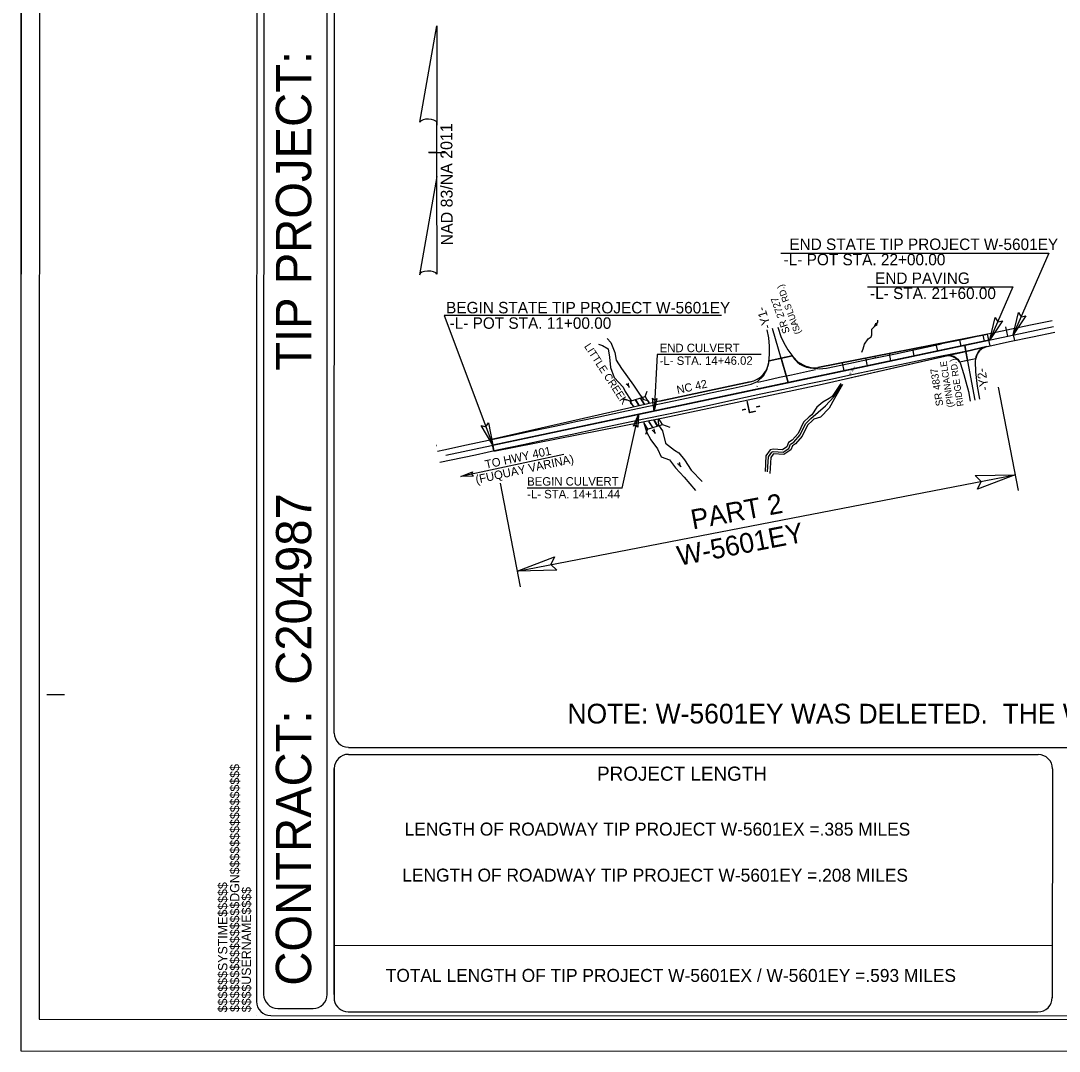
# Model space of a CAD drawing. Extents: x 2105791 to 2114488, y 667759 to 673441.
# Drawn here: x 2105791 to 2109589, y 667759 to 671528 of the extents above; entities that cross this region are included whole.
import ezdxf

# ---------------------------------------------------------------- set-up
doc = ezdxf.new("R2010")
doc.units = 0
for name, color, linetype in [('Default', 7, 'Continuous'), ('Exist Hydro Jurisdictional Stream or Body of Water', 7, 'Continuous'), ('Exist Hydro Stream Flow Arrow CELL', 7, 'Continuous'), ('Exist Hydro Stream or Body of Water', 7, 'Continuous'), ('Exist Roads EOP', 7, 'Continuous'), ('Exist Structure Minor Pipes RCP 48 Inch Text', 7, 'Continuous'), ('Old_Level_1', 7, 'Continuous'), ('Prop Dimension', 7, 'Continuous'), ('Prop Dimension Text', 7, 'Continuous'), ('Prop DSN Text', 7, 'Continuous'), ('Prop EOT', 7, 'Continuous'), ('Prop Horizontal Alignment', 7, 'Continuous'), ('Prop North Arrow NAD83 for Plan Sheets CELL', 7, 'Continuous'), ('Prop Shade Light', 7, 'Continuous'), ('Scratch_Level_3', 7, 'Continuous'), ('Sheet Cutting Line CELL', 7, 'Continuous'), ('Sheet Data Field CELL', 7, 'Continuous'), ('Sheet Plot Border Inside CELL', 7, 'Continuous'), ('Sheet Plot Border Outside CELL', 7, 'Continuous'), ('Sheet Title CELL', 7, 'Continuous'), ('Typical Terminator CELL', 7, 'Continuous')]:
    doc.layers.add(name, color=color, linetype=linetype)

msp = doc.modelspace()

# ---------------------------------------------------------------- linework, layer by layer
at = {"layer": 'Default'}
msp.add_arc((2108867.2, 670316.4), 52.5, 335.702, 340.6416, dxfattribs=at)
at = {"layer": 'Exist Hydro Jurisdictional Stream or Body of Water'}
for points in [[(2108867.2, 670316.4), (2108871.4, 670328.4), (2108876.9, 670345.1), (2108890.4, 670364.5), (2108901, 670372.3), (2108904.2, 670379.1), (2108903.8, 670400.7), (2108916, 670412.7), (2108926.2, 670426.1), (2108925.7, 670433.4)], [(2107935.6, 670365.5), (2107949, 670351.7), (2107964.3, 670314.3), (2107968.2, 670286.5), (2107988.4, 670255.8), (2108010.6, 670226.4), (2108032.1, 670194.8), (2108056.2, 670158.6), (2108069, 670143.1), (2108085.6, 670139.7), (2108089.3, 670128.6)], [(2107903.4, 670345.8), (2107918.5, 670340.3), (2107939.8, 670328.5), (2107944.2, 670298.1), (2107948.2, 670260), (2107961, 670223.9), (2107994.4, 670187.5), (2108001.1, 670172.4), (2108021.7, 670140.9), (2108022.4, 670133.9), (2108021.4, 670129.5), (2108027.8, 670122.3), (2108033.3, 670118)], [(2108070.2, 670057.1), (2108079.6, 670025.3), (2108094.8, 669995.7), (2108120.3, 669962), (2108133.4, 669933.8), (2108163.2, 669922.3), (2108185.5, 669893.1), (2108216.9, 669859), (2108259.2, 669809.7)], [(2108120.8, 670069.8), (2108121.8, 670065.2), (2108122.9, 670048.8), (2108138, 670028.9), (2108149.5, 669983.5), (2108181.7, 669958.1), (2108198.3, 669947.7), (2108218.1, 669921.8), (2108242.6, 669885.1), (2108282.7, 669843.6)]]:
    msp.add_lwpolyline(points, dxfattribs=at)
at = {"layer": 'Exist Hydro Stream Flow Arrow CELL'}
for p, q in [((2108914.9, 670412.4), (2108914.9, 670412.4)), ((2108012.4, 670194.9), (2108012.4, 670194.9)), ((2108107.5, 670025.8), (2108107.5, 670025.8)), ((2108200.3, 669904.1), (2108200.3, 669904.1))]:
    msp.add_line(p, q, dxfattribs=at)
for points in [[(2108917.6, 670421.6), (2108916.9, 670419.2), (2108915.9, 670416.8), (2108914.8, 670414.4), (2108913.6, 670412.2), (2108912.2, 670410), (2108910.7, 670407.8), (2108909.2, 670405.8)], [(2108923.7, 670416.4), (2108921.3, 670415.3), (2108919.1, 670413.9), (2108916.9, 670412.6), (2108914.9, 670411.1), (2108912.9, 670409.4), (2108910.9, 670407.6), (2108909.2, 670405.8)], [(2108004.7, 670200.6), (2108006.8, 670199.1), (2108008.7, 670197.3), (2108010.5, 670195.5), (2108012.2, 670193.6), (2108013.8, 670191.5), (2108015.3, 670189.4), (2108016.6, 670187.2)], [(2108011.7, 670204.5), (2108011.9, 670201.9), (2108012.4, 670199.3), (2108012.9, 670196.8), (2108013.6, 670194.4), (2108014.5, 670191.9), (2108015.5, 670189.5), (2108016.6, 670187.2)], [(2108099.7, 670031.4), (2108101.7, 670029.9), (2108103.7, 670028.1), (2108105.6, 670026.4), (2108107.3, 670024.5), (2108108.9, 670022.5), (2108110.4, 670020.3), (2108111.8, 670018.2)], [(2108106.6, 670035.4), (2108106.9, 670032.8), (2108107.4, 670030.3), (2108108, 670027.7), (2108108.7, 670025.3), (2108109.6, 670022.9), (2108110.6, 670020.5), (2108111.8, 670018.2)], [(2108192.5, 669909.7), (2108194.5, 669908.2), (2108196.5, 669906.4), (2108198.4, 669904.6), (2108200.1, 669902.7), (2108201.7, 669900.7), (2108203.2, 669898.6), (2108204.6, 669896.4)], [(2108199.4, 669913.6), (2108199.7, 669911.1), (2108200.2, 669908.5), (2108200.8, 669906), (2108201.5, 669903.6), (2108202.4, 669901.1), (2108203.4, 669898.7), (2108204.6, 669896.4)]]:
    msp.add_lwpolyline(points, dxfattribs=at)
at = {"layer": 'Exist Hydro Stream or Body of Water'}
for p, q in [((2108790.2, 670201.1), (2108758.5, 670154.2)), ((2108796.2, 670197.5), (2108767.7, 670146.6)), ((2108724.2, 670133.5), (2108703, 670115.3)), ((2108703, 670115.3), (2108683.7, 670087.3)), ((2108715.6, 670077.9), (2108691.8, 670071.1))]:
    msp.add_line(p, q, dxfattribs=at)
for points in [[(2108680.9, 670073.2), (2108734, 670119.7), (2108764.3, 670153.3), (2108777, 670170.9), (2108793.1, 670198.7)], [(2108758.5, 670154.2), (2108747.2, 670146.1), (2108724.2, 670133.5)], [(2108767.7, 670146.6), (2108767.7, 670146.6), (2108747.4, 670111)], [(2108747.4, 670111), (2108715.6, 670077.9)], [(2108683.7, 670087.3), (2108675, 670079.6), (2108653.6, 670059.8), (2108633.8, 670018.4), (2108612.5, 669993.9), (2108599.3, 669985.3), (2108592.9, 669970), (2108577, 669959.4), (2108542.3, 669961.3), (2108532.2, 669958.4), (2108516.6, 669936.7), (2108513.8, 669879.1)], [(2108691.8, 670071.1), (2108686.7, 670066.7), (2108668, 670049.2), (2108648.5, 670008.7), (2108624, 669980.5), (2108613.4, 669973.6), (2108607.1, 669958.5), (2108581.9, 669941.5), (2108544.2, 669943.7), (2108542.9, 669943.3), (2108533.9, 669930.7), (2108531, 669872.8)], [(2108579.4, 669950.4), (2108579.4, 669950.4), (2108600, 669964.3), (2108606.3, 669979.5), (2108618.2, 669987.2), (2108641.1, 670013.5), (2108660.8, 670054.5), (2108680.9, 670073.2)], [(2108522.5, 669878.7), (2108525.2, 669933.7), (2108537.5, 669950.9), (2108543.3, 669952.5), (2108579.4, 669950.4)]]:
    msp.add_lwpolyline(points, dxfattribs=at)
at = {"layer": 'Exist Roads EOP'}
for points in [[(2107314.7, 669954), (2107338.6, 669959.2), (2107421.5, 669977.3), (2107501.1, 669994), (2107583.8, 670011.2), (2107661.5, 670028.3), (2107744.5, 670046), (2107827, 670063.4), (2107905.3, 670079.8), (2107989.2, 670097.4), (2108069.8, 670114.8), (2108150.1, 670132), (2108231.9, 670149.3), (2108314.1, 670167.1), (2108396.2, 670184.8), (2108462.7, 670199.1), (2108486, 670209.3), (2108507.3, 670229.4), (2108520.3, 670254.1), (2108527.3, 670279.6), (2108530, 670308), (2108529.7, 670338.5), (2108527, 670368.5), (2108521.1, 670397.2)], [(2108559.4, 670407.5), (2108570.6, 670374), (2108581.5, 670350.3), (2108596.6, 670325.2), (2108614.4, 670300.5), (2108634.4, 670279.1), (2108662, 670264.9), (2108690, 670257.1), (2108710.7, 670255.1), (2108738.2, 670257.6), (2108819.7, 670274.9), (2108905, 670292.6), (2108989.7, 670310.6), (2109074.1, 670328.3), (2109158.7, 670346.2)], [(2109563.8, 670431.3), (2109483.4, 670414.5), (2109397.7, 670396.6), (2109310.7, 670378.5), (2109238.7, 670362.8), (2109158.7, 670346.2)], [(2109170.6, 670304.6), (2109183.6, 670307.3), (2109246.2, 670320.3), (2109320.4, 670335.6), (2109407, 670354.7), (2109491.5, 670372.5), (2109572.5, 670389.6)], [(2109170.6, 670304.6), (2109183.6, 670307.3), (2109246.2, 670320.3), (2109320.4, 670335.6), (2109407, 670354.7), (2109491.5, 670372.5), (2109572.5, 670389.6)], [(2109298.5, 670143.9), (2109290.6, 670191.6), (2109284.6, 670244), (2109283.1, 670282.4), (2109285.8, 670301.9), (2109295.1, 670321), (2109301.7, 670326.8), (2109317.8, 670334.5)], [(2109170.6, 670304.5), (2109092.9, 670288.3), (2109012.1, 670271.1), (2108929.6, 670253.7), (2108836.6, 670233.9), (2108753.2, 670216), (2108668.6, 670198.6), (2108581.2, 670179.9), (2108498.1, 670162.3), (2108414.1, 670143.9), (2108331.9, 670126.2), (2108247.6, 670108), (2108159.9, 670089.8), (2108070, 670071), (2107982.8, 670052.5), (2107896.4, 670034.2), (2107808.1, 670015.5), (2107717.3, 669996.3), (2107628.3, 669977.1), (2107539.6, 669958.4), (2107453.9, 669939.9), (2107365.5, 669921.4), (2107323.4, 669912.2)], [(2109183.8, 670306.4), (2109203.3, 670301.7), (2109217.9, 670290.7), (2109226.5, 670276.5), (2109240.5, 670234.4), (2109248, 670207.5), (2109256.7, 670172.2), (2109263.6, 670137.3)], [(2108698, 670251.8), (2108653.6, 670241.7), (2108610, 670232.4), (2108565.9, 670223), (2108520.1, 670212.6), (2108486.3, 670205.4)], [(2108698, 670251.8), (2108653.6, 670241.7), (2108610, 670232.4), (2108565.9, 670223), (2108520.1, 670212.6), (2108486.3, 670205.4)]]:
    msp.add_lwpolyline(points, dxfattribs=at)
at = {"layer": 'Old_Level_1'}
for p, q in [((2107250.5, 671157.5), (2107312.9, 671509.5)), ((2107313.2, 671509.5), (2107312.9, 671509.5)), ((2107313.2, 671509.5), (2107312.9, 671509.5)), ((2107313.2, 671509.5), (2107313.1, 671146.5)), ((2107313.1, 670958.2), (2107313.1, 671157.1)), ((2107313.1, 671146.5), (2107313.1, 671156.8)), ((2107282.7, 671046.3), (2107282.4, 671046.3)), ((2107309.7, 671046.3), (2107282.7, 671046.3)), ((2107283.1, 671046.3), (2107343.9, 671046.3)), ((2107313.1, 670958.2), (2107249.6, 670599.4)), ((2107313.4, 670600.9), (2107313.1, 670958.2)), ((2109365.4, 670188.3), (2109438.5, 669810.2)), ((2107606, 669515.5), (2109427.4, 669867.4)), ((2107544, 669836.4), (2107617.1, 669458.2))]:
    msp.add_line(p, q, dxfattribs=at)
for centre, start_param, end_param in [((2107281.9, 671153.8), 0.216388, 2.908219), ((2107281.7, 670598.1), 0.201328, 3.141593)]:
    msp.add_ellipse(centre, major_axis=(32.1, -0.2), ratio=0.461098, start_param=start_param, end_param=end_param, dxfattribs=at)
at = {"layer": 'Prop Dimension'}
for p, q in [((2108074.6, 670153.4), (2108082.2, 670173.4)), ((2108020, 670136.9), (2107993.4, 670146.9)), ((2108020, 670136.9), (2108074.6, 670153.4)), ((2108033.1, 670116.3), (2108020, 670136.9)), ((2108037.6, 670142.2), (2108051.3, 670120.1)), ((2108038.8, 670142.6), (2108052.5, 670120.4)), ((2108056.2, 670147.8), (2108070.7, 670124.3)), ((2108057.1, 670148.1), (2108071.7, 670124.5)), ((2108074.6, 670153.4), (2108089.9, 670128.4)), ((2108069, 670058.5), (2108083.2, 670035)), ((2108087.2, 670062.4), (2108100.9, 670040.3)), ((2108088.2, 670062.6), (2108101.8, 670040.6)), ((2108106.4, 670066.5), (2108119.1, 670045.9)), ((2108107.6, 670066.8), (2108120.3, 670046.2)), ((2108137.8, 670051.5), (2108125.7, 670070.7)), ((2108083.2, 670035), (2108075.6, 670014.9)), ((2108083.2, 670035), (2108137.8, 670051.5)), ((2108137.8, 670051.5), (2108164.4, 670041.5))]:
    msp.add_line(p, q, dxfattribs=at)
at = {"layer": 'Prop Dimension Text'}
for p, q in [((2108118.6, 670307.3), (2108107.2, 670100.6)), ((2108498.4, 670307.2), (2108118.6, 670307.3)), ((2107990, 669818.3), (2108050.3, 670088.5)), ((2107777.1, 669942), (2107400, 669860.9)), ((2107990, 669818.3), (2107643.2, 669818.4))]:
    msp.add_line(p, q, dxfattribs=at)
at = {"layer": 'Prop DSN Text'}
for p, q in [((2108570.8, 670678.8), (2109551.4, 670678.7)), ((2109551.4, 670678.7), (2109420.8, 670379.1)), ((2108887.3, 670555.2), (2109419.8, 670555.1)), ((2109419.8, 670555.1), (2109335.2, 670361)), ((2108354.4, 670450.5), (2107339.1, 670450.6)), ((2107339.1, 670450.6), (2107517.2, 669975.5)), ((2109420.8, 670379.1), (2109425.2, 670358.5))]:
    msp.add_line(p, q, dxfattribs=at)
at = {"layer": 'Prop EOT'}
for p, q in [((2108706, 670259.8), (2109327.2, 670381.9)), ((2109336.3, 670339.1), (2109327.2, 670381.9)), ((2108722.4, 670198.8), (2109336.3, 670339.1)), ((2108527.8, 670284.6), (2108612.9, 670302.6)), ((2109224.1, 670280.4), (2109284.6, 670293.2)), ((2108126.9, 670137), (2108458.8, 670207.2)), ((2108140, 670075.4), (2108722.4, 670198.8)), ((2108484.4, 670190.6), (2108485.8, 670192.7)), ((2108126.9, 670137), (2107512.7, 669996.4)), ((2107521.6, 669954.5), (2108140, 670075.4)), ((2107521.6, 669954.5), (2107512.7, 669996.4))]:
    msp.add_line(p, q, dxfattribs=at)
for centre, radius, start, end in [((2109336.5, 670285.3), 52.5, 102.8715, 171.362), ((2108440.7, 670292.8), 87.5, 281.9495, 354.576), ((2108689.1, 670345.7), 87.5, 209.4773, 281.1199), ((2109181.4, 670249.9), 52.5, 35.5249, 102.8715)]:
    msp.add_arc(centre, radius, start, end, dxfattribs=at)
at = {"layer": 'Prop Horizontal Alignment'}
for p, q in [((2107346, 669939.2), (2109567.8, 670410.3)), ((2108597.8, 670204.6), (2108540.4, 670402.2)), ((2109281.1, 670140.9), (2109243.7, 670341.6))]:
    msp.add_line(p, q, dxfattribs=at)
at = {"layer": 'Prop Shade Light'}
for p, q in [((2109327.2, 670381.9), (2108706, 670259.8)), ((2109331.8, 670360.3), (2109243.7, 670341.6)), ((2109243.7, 670341.6), (2109331.8, 670360.3)), ((2109331.8, 670360.3), (2109327.2, 670381.9)), ((2109336.3, 670339.1), (2109331.8, 670360.3)), ((2108597.8, 670204.6), (2109243.7, 670341.6)), ((2109248, 670318.9), (2109243.7, 670341.6)), ((2109243.7, 670341.6), (2109248, 670318.9)), ((2109324.8, 670336.5), (2109248, 670318.9)), ((2108571.8, 670293.9), (2108527.8, 670284.6)), ((2108612.9, 670302.6), (2108571.8, 670293.9)), ((2108597.8, 670204.6), (2108571.8, 670293.9)), ((2108571.8, 670293.9), (2108597.8, 670204.6)), ((2109248, 670318.9), (2109169.7, 670301)), ((2109224.1, 670280.4), (2109254, 670286.7)), ((2109248, 670318.9), (2109254, 670286.7)), ((2109254, 670286.7), (2109248, 670318.9)), ((2109254, 670286.7), (2109284.6, 670293.2)), ((2108458.8, 670207.2), (2108126.9, 670137)), ((2107517.2, 669975.5), (2108597.8, 670204.6)), ((2108140, 670075.4), (2108722.4, 670198.8)), ((2108126.9, 670137), (2107513.2, 669996.5)), ((2107521.6, 669954.5), (2108140, 670075.4)), ((2107513.2, 669996.5), (2107517.2, 669975.5)), ((2107517.2, 669975.5), (2107521.6, 669954.5))]:
    msp.add_line(p, q, dxfattribs=at)
for points in [[(2109243.7, 670341.6), (2108597.8, 670204.6), (2107517.2, 669975.5)], [(2109248, 670318.9), (2109324.8, 670336.5), (2109336.3, 670339.1)], [(2108722.4, 670198.8), (2109169.7, 670301), (2109248, 670318.9)]]:
    msp.add_lwpolyline(points, dxfattribs=at)
for centre, radius, start, end in [((2109336.5, 670285.3), 52.5, 102.8715, 171.362), ((2108440.7, 670292.8), 87.5, 281.9495, 354.576), ((2108689.1, 670345.7), 87.5, 209.4773, 281.1199), ((2109181.4, 670249.9), 52.5, 35.5249, 102.8715)]:
    msp.add_arc(centre, radius, start, end, dxfattribs=at)
at = {"layer": 'Scratch_Level_3'}
for p, q in [((2109393, 670409), (2109400.3, 670374.8)), ((2109224.2, 670361.7), (2109229.1, 670338.5)), ((2109310.1, 670378.3), (2109314.7, 670356.6)), ((2109052.4, 670327.9), (2109057.9, 670302.2)), ((2109138.3, 670344.8), (2109143.5, 670320.3)), ((2108880.7, 670294.2), (2108886.7, 670265.9)), ((2108966.6, 670311), (2108972.3, 670284)), ((2108794.8, 670277.3), (2108801.1, 670247.7))]:
    msp.add_line(p, q, dxfattribs=at)
at = {"layer": 'Sheet Cutting Line CELL'}
msp.add_line((2105792, 673440.8), (2105791, 667760.7), dxfattribs=at)
at = {"layer": 'Sheet Data Field CELL'}
msp.add_line((2106653.4, 667889.7), (2106653.4, 667889.7), dxfattribs=at)
at = {"layer": 'Sheet Plot Border Inside CELL'}
msp.add_lwpolyline([(2105858.2, 667876.6), (2114463.6, 667875.1), (2114464.5, 673323.4), (2105859.1, 673324.8)], close=True, dxfattribs=at)
at = {"layer": 'Sheet Plot Border Outside CELL'}
msp.add_lwpolyline([(2114487.7, 673439.3), (2105792, 673440.8), (2105791, 667760.7), (2114486.8, 667759.2)], close=True, dxfattribs=at)
at = {"layer": 'Sheet Title CELL'}
for p, q in [((2106911.6, 667967.1), (2106912.5, 673234.1)), ((2106937.6, 668922.4), (2106938.3, 673234.1)), ((2105886.8, 669064.5), (2105951.3, 669064.5)), ((2106989.2, 668870.7), (2114321.7, 668869.5)), ((2106989.2, 668844.8), (2109512.2, 668844.4)), ((2106937.5, 668793.3), (2106937.4, 667945.6)), ((2106937.5, 667967), (2106937.5, 668793.3)), ((2109564.4, 668791.8), (2109563.5, 667955.1)), ((2106937.5, 668146.9), (2109563.9, 668146.5)), ((2106653.4, 667889.7), (2106653.4, 667889.7)), ((2106653.4, 667889.7), (2106653.4, 667889.7)), ((2106653.4, 667889.7), (2106653.4, 667889.7)), ((2106653.4, 667889.7), (2106653.4, 667889.7))]:
    msp.add_line(p, q, dxfattribs=at)
for points in [[(2106654.3, 673260), (2106653.4, 667941.3)], [(2106654.3, 673260), (2106653.4, 667941.3)], [(2106680.2, 673234.1), (2106679.2, 667967.1)], [(2106730.8, 667915.5), (2106859.9, 667915.4)], [(2106988.2, 667903.6), (2109511.2, 667903.1)], [(2106705, 667889.6), (2114347.4, 667888.3)]]:
    msp.add_lwpolyline(points, dxfattribs=at)
for centre, radius, start, end in [((2106989.2, 668922.6), 51.6, 179.9903, 269.9903), ((2106989.2, 668793.5), 51.6, 89.9903, 179.9903), ((2109512.1, 668792.1), 52.3, 359.9376, 89.9376), ((2106730.9, 667967.3), 51.6, 179.9903, 269.9903), ((2106860, 667967.3), 51.6, 269.9903, 359.9903), ((2106705, 667941.5), 51.6, 179.9903, 269.9903), ((2106988.2, 667955.2), 51.6, 190.4989, 269.9903), ((2109511.2, 667955.4), 52.3, 269.9376, 359.9376)]:
    msp.add_arc(centre, radius, start, end, dxfattribs=at)
at = {"layer": 'Typical Terminator CELL'}
for points in [[(2109381, 670430.5), (2109335.2, 670361), (2109354.8, 670442.4), (2109364, 670427)], [(2109466.6, 670448.7), (2109420.8, 670379.1), (2109440.4, 670460.6), (2109449.6, 670445.1)], [(2108117.6, 670146.2), (2108107.2, 670100.6), (2108101.5, 670147.4), (2108109.4, 670141)], [(2107501.6, 670057.3), (2107517.2, 669975.5), (2107474.6, 670047.6), (2107491.9, 670042.9)], [(2108032.5, 670045.3), (2108050.3, 670088.5), (2108048.2, 670041.5), (2108041.5, 670049)], [(2107311.4, 669974.7), (2107310.6, 669974.7), (2107311.3, 669975), (2107311.3, 669974.9)], [(2107311.4, 669974.7), (2107310.6, 669974.7), (2107311.3, 669975), (2107311.3, 669974.9)], [(2107446.8, 669862.8), (2107400, 669860.9), (2107443.6, 669878.6), (2107439.6, 669869.4)], [(2109281.8, 669864.5), (2109427.4, 669867.4), (2109290.6, 669815), (2109303.7, 669843.5)], [(2107751.7, 669518.4), (2107606, 669515.5), (2107742.9, 669567.9), (2107729.8, 669539.4)]]:
    msp.add_lwpolyline(points, close=True, dxfattribs=at)

# ---------------------------------------------------------------- texts
at = {"layer": 'Exist Structure Minor Pipes RCP 48 Inch Text'}
msp.add_text('48" RCP', height=7, rotation=57.9437, dxfattribs=at).set_placement((2108824.6, 670229.8))
at = {"layer": 'Old_Level_1'}
for s, height, rotation, p in [('PART 2', 72.35, 10.5239, (2108249.1, 669667.3)), ('W-5601EY', 72.35, 10.8677, (2108199.2, 669534.5)), ('NOTE: W-5601EY WAS DELETED.  THE WORK FROM W-5601EY WAS INCORPORATED INTO W-5601EX.', 72.352, 360, (2107790.5, 668957.8))]:
    msp.add_text(s, height=height, rotation=rotation, dxfattribs=at).set_placement(p)
at = {"layer": 'Prop Dimension Text'}
for s, height, rotation, p in [('(SAULS RD.)', 24.026, 110.3311, (2108645.1, 670387)), ('SR 2727', 26.7, 109.3971, (2108604.6, 670389.5)), ('-Y1-', 32.55, 107.1262, (2108536.3, 670406.5)), ('LITTLE CREEK', 27.562, 303.2275, (2107850.4, 670337.3)), ('END CULVERT', 31.008, 0.1263, (2108127.8, 670315.9)), ('-L- STA. 14+46.02', 31.008, 0.1263, (2108127.9, 670269.3)), ('(PINNACLE ', 24.03, 99.0507, (2109203.7, 670116.4)), ('RIDGE RD.)', 24.03, 99.0507, (2109239.6, 670119.7)), ('SR 4837', 26.7, 99.0507, (2109165.3, 670121.1)), ('-Y2-', 32.55, 98.991, (2109331.6, 670178.2)), ('NC 42 ', 29.77, 12.3046, (2108193.5, 670163.1)), ('-L-', 44.65, 11.9935, (2108429.8, 670087.2)), ('(FUQUAY VARINA)', 31.008, 12.1755, (2107457.8, 669834.5)), ('TO HWY 401', 31.01, 12.1755, (2107492.3, 669889.5)), ('BEGIN CULVERT', 31.008, 0.1263, (2107643.2, 669827.7)), ('-L- STA. 14+11.44', 31.008, 0.1263, (2107643.3, 669781.2))]:
    msp.add_text(s, height=height, rotation=rotation, dxfattribs=at).set_placement(p)
at = {"layer": 'Prop DSN Text'}
for s, height, p in [('END STATE TIP PROJECT W-5601EY', 42, (2108602, 670689.8)), ('-L- POT STA. 22+00.00', 42, (2108581.1, 670634)), ('END PAVING', 42, (2108915.5, 670565.5)), ('-L- STA. 21+60.00', 42, (2108897.1, 670510.5)), ('BEGIN STATE TIP PROJECT W-5601EY', 42, (2107346.6, 670458.1)), ('-L- POT STA. 11+00.00', 42, (2107359.2, 670401.6)), ('LENGTH OF ROADWAY TIP PROJECT W-5601EX =.385 MILES', 47.447, (2107194.9, 668548.1)), ('LENGTH OF ROADWAY TIP PROJECT W-5601EY =.208 MILES', 47.447, (2107186.6, 668379.7)), ('TOTAL LENGTH OF TIP PROJECT W-5601EX / W-5601EY =.593 MILES', 47.447, (2107125.9, 668013))]:
    msp.add_text(s, height=height, rotation=359.9872, dxfattribs=at).set_placement(p)
at = {"layer": 'Prop North Arrow NAD83 for Plan Sheets CELL'}
msp.add_text('NAD 83/NA 2011', height=43.531, rotation=90.2864, dxfattribs=at).set_placement((2107371.4, 670706.6))
at = {"layer": 'Sheet Title CELL'}
for s, height, rotation, p in [('TIP PROJECT:', 129.094, 89.9903, (2106853.2, 670247.8)), ('C204987', 129.09, 89.9903, (2106853.5, 669099.5)), ('CONTRACT:', 129.09, 89.9903, (2106853, 667998.9)), ('$$$$$$$$$$$$$$$$DGN$$$$$$$$$$$$$$$$', 33.887, 89.9903, (2106590.3, 667902.6)), ('PROJECT LENGTH', 51.635, 359.9903, (2107898.6, 668748.7)), ('$$$$$$SYSTIME$$$$$', 33.887, 89.9903, (2106546.4, 667901.4)), ('$$$$USERNAME$$$$', 33.887, 89.9903, (2106632.7, 667901.7))]:
    msp.add_text(s, height=height, rotation=rotation, dxfattribs=at).set_placement(p)

doc.saveas('drawing.dxf')
